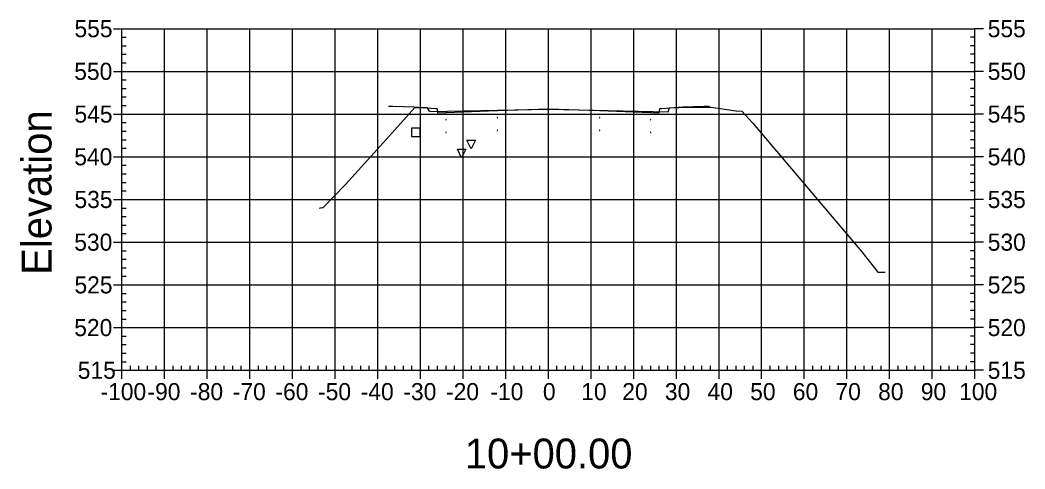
# Model space of a CAD drawing. Extents: x 708103 to 717568, y 374476 to 378707.
# Drawn here: x 708103.1 to 708338.7, y 376801.5 to 376906.6 of the extents above; entities that cross this region are included whole.
import ezdxf

# ---------------------------------------------------------------- set-up
doc = ezdxf.new("R2010")
doc.units = 0
for name, color, linetype in [('1', 7, 'Continuous'), ('10', 7, 'Continuous'), ('14', 7, 'Continuous'), ('22', 7, 'Continuous'), ('57', 7, 'Continuous'), ('60', 7, 'Continuous'), ('Existing', 7, 'Continuous')]:
    doc.layers.add(name, color=color, linetype=linetype)

msp = doc.modelspace()

# ---------------------------------------------------------------- linework, layer by layer
for points in [[(708226.93, 376885.12), (708227.03, 376885.12), (708227.03, 376885.22), (708226.93, 376885.22)], [(708202.93, 376883.28), (708203.03, 376883.28), (708203.03, 376883.38), (708202.93, 376883.38)], [(708214.93, 376883.76), (708215.03, 376883.76), (708215.03, 376883.86), (708214.93, 376883.86)], [(708226.93, 376884.12), (708227.03, 376884.12), (708227.03, 376884.22), (708226.93, 376884.22)], [(708238.93, 376883.76), (708239.03, 376883.76), (708239.03, 376883.86), (708238.93, 376883.86)], [(708250.93, 376883.28), (708251.03, 376883.28), (708251.03, 376883.38), (708250.93, 376883.38)], [(708202.93, 376880.28), (708203.03, 376880.28), (708203.03, 376880.38), (708202.93, 376880.38)], [(708214.93, 376880.76), (708215.03, 376880.76), (708215.03, 376880.86), (708214.93, 376880.86)], [(708226.93, 376881.12), (708227.03, 376881.12), (708227.03, 376881.22), (708226.93, 376881.22)], [(708238.93, 376880.76), (708239.03, 376880.76), (708239.03, 376880.86), (708238.93, 376880.86)], [(708250.93, 376880.28), (708251.03, 376880.28), (708251.03, 376880.38), (708250.93, 376880.38)]]:
    msp.add_lwpolyline(points, close=True)
at = {"layer": '1'}
for points in [[(708208.89, 376876.52), (708207.89, 376878.52), (708209.89, 376878.52)], [(708206.64, 376874.41), (708205.64, 376876.41), (708207.64, 376876.41)]]:
    msp.add_lwpolyline(points, close=True, dxfattribs=at)
at = {"layer": '10'}
msp.add_lwpolyline([(708194.88, 376879.34), (708196.88, 376879.34), (708196.88, 376881.34), (708194.88, 376881.34)], close=True, dxfattribs=at)
at = {"layer": '14'}
for points in [[(708202.98, 376884.99), (708202.98, 376885.04), (708202.98, 376884.99), (708202.93, 376884.99), (708202.98, 376884.99), (708202.98, 376884.94), (708202.98, 376884.99), (708203.03, 376884.99)], [(708214.98, 376885.47), (708214.98, 376885.52), (708214.98, 376885.47), (708214.93, 376885.47), (708214.98, 376885.47), (708214.98, 376885.42), (708214.98, 376885.47), (708215.03, 376885.47)], [(708226.98, 376885.83), (708226.98, 376885.88), (708226.98, 376885.83), (708226.93, 376885.83), (708226.98, 376885.83), (708226.98, 376885.78), (708226.98, 376885.83), (708227.03, 376885.83)], [(708238.98, 376885.47), (708238.98, 376885.52), (708238.98, 376885.47), (708238.93, 376885.47), (708238.98, 376885.47), (708238.98, 376885.42), (708238.98, 376885.47), (708239.03, 376885.47)], [(708250.98, 376884.99), (708250.98, 376885.04), (708250.98, 376884.99), (708250.93, 376884.99), (708250.98, 376884.99), (708250.98, 376884.94), (708250.98, 376884.99), (708251.03, 376884.99)], [(708264.7, 376886.26), (708264.7, 376886.31), (708264.7, 376886.26), (708264.65, 376886.26), (708264.7, 376886.26), (708264.7, 376886.21), (708264.7, 376886.26), (708264.75, 376886.26)]]:
    msp.add_lwpolyline(points, dxfattribs=at)
at = {"layer": '22'}
msp.add_lwpolyline([(708189.48, 376886.47), (708190.48, 376886.51), (708195.48, 376886.31), (708200.48, 376885.91), (708200.9, 376885.91), (708200.98, 376884.91), (708202.98, 376884.99), (708214.98, 376885.47), (708226.98, 376885.83), (708238.98, 376885.47), (708250.98, 376884.99), (708252.98, 376884.91), (708253.07, 376885.91), (708253.48, 376885.91), (708258.48, 376886.31), (708263.48, 376886.51), (708264.48, 376886.47), (708264.7, 376886.26)], dxfattribs=at)
at = {"layer": '57'}
for p, q in [((708124.98, 376904.63), (708126.98, 376904.63)), ((708126.98, 376904.63), (708326.98, 376904.63)), ((708126.98, 376824.63), (708126.98, 376904.63)), ((708126.98, 376824.63), (708126.98, 376904.63)), ((708136.98, 376824.63), (708136.98, 376904.63)), ((708146.98, 376824.63), (708146.98, 376904.63)), ((708156.98, 376824.63), (708156.98, 376904.63)), ((708166.98, 376824.63), (708166.98, 376904.63)), ((708176.98, 376824.63), (708176.98, 376904.63)), ((708186.98, 376824.63), (708186.98, 376904.63)), ((708196.98, 376824.63), (708196.98, 376904.63)), ((708206.98, 376824.63), (708206.98, 376904.63)), ((708216.98, 376824.63), (708216.98, 376904.63)), ((708226.98, 376824.63), (708226.98, 376904.63)), ((708236.98, 376824.63), (708236.98, 376904.63)), ((708246.98, 376824.63), (708246.98, 376904.63)), ((708256.98, 376824.63), (708256.98, 376904.63)), ((708266.98, 376824.63), (708266.98, 376904.63)), ((708276.98, 376824.63), (708276.98, 376904.63)), ((708286.98, 376824.63), (708286.98, 376904.63)), ((708296.98, 376824.63), (708296.98, 376904.63)), ((708306.98, 376824.63), (708306.98, 376904.63)), ((708316.98, 376824.63), (708316.98, 376904.63)), ((708326.98, 376824.63), (708326.98, 376904.63)), ((708326.98, 376824.63), (708326.98, 376904.63)), ((708328.98, 376904.63), (708326.98, 376904.63)), ((708126.98, 376902.63), (708127.98, 376902.63)), ((708326.98, 376902.63), (708325.98, 376902.63)), ((708126.98, 376900.63), (708127.98, 376900.63)), ((708126.98, 376898.63), (708127.98, 376898.63)), ((708326.98, 376900.63), (708325.98, 376900.63)), ((708326.98, 376898.63), (708325.98, 376898.63)), ((708126.98, 376896.63), (708127.98, 376896.63)), ((708326.98, 376896.63), (708325.98, 376896.63)), ((708124.98, 376894.63), (708126.98, 376894.63)), ((708126.98, 376894.63), (708326.98, 376894.63)), ((708328.98, 376894.63), (708326.98, 376894.63)), ((708126.98, 376892.63), (708127.98, 376892.63)), ((708326.98, 376892.63), (708325.98, 376892.63)), ((708126.98, 376890.63), (708127.98, 376890.63)), ((708326.98, 376890.63), (708325.98, 376890.63)), ((708126.98, 376888.63), (708127.98, 376888.63)), ((708326.98, 376888.63), (708325.98, 376888.63)), ((708124.98, 376884.63), (708126.98, 376884.63)), ((708126.98, 376886.63), (708127.98, 376886.63)), ((708126.98, 376884.63), (708326.98, 376884.63)), ((708326.98, 376886.63), (708325.98, 376886.63)), ((708328.98, 376884.63), (708326.98, 376884.63)), ((708126.98, 376882.63), (708127.98, 376882.63)), ((708326.98, 376882.63), (708325.98, 376882.63)), ((708126.98, 376880.63), (708127.98, 376880.63)), ((708326.98, 376880.63), (708325.98, 376880.63)), ((708126.98, 376878.63), (708127.98, 376878.63)), ((708326.98, 376878.63), (708325.98, 376878.63)), ((708126.98, 376876.63), (708127.98, 376876.63)), ((708326.98, 376876.63), (708325.98, 376876.63)), ((708124.98, 376874.63), (708126.98, 376874.63)), ((708126.98, 376874.63), (708326.98, 376874.63)), ((708328.98, 376874.63), (708326.98, 376874.63)), ((708126.98, 376872.63), (708127.98, 376872.63)), ((708126.98, 376870.63), (708127.98, 376870.63)), ((708326.98, 376872.63), (708325.98, 376872.63)), ((708326.98, 376870.63), (708325.98, 376870.63)), ((708126.98, 376868.63), (708127.98, 376868.63)), ((708326.98, 376868.63), (708325.98, 376868.63)), ((708126.98, 376866.63), (708127.98, 376866.63)), ((708326.98, 376866.63), (708325.98, 376866.63)), ((708124.98, 376864.63), (708126.98, 376864.63)), ((708126.98, 376864.63), (708326.98, 376864.63)), ((708328.98, 376864.63), (708326.98, 376864.63)), ((708126.98, 376862.63), (708127.98, 376862.63)), ((708326.98, 376862.63), (708325.98, 376862.63)), ((708126.98, 376860.63), (708127.98, 376860.63)), ((708126.98, 376858.63), (708127.98, 376858.63)), ((708326.98, 376860.63), (708325.98, 376860.63)), ((708326.98, 376858.63), (708325.98, 376858.63)), ((708126.98, 376856.63), (708127.98, 376856.63)), ((708326.98, 376856.63), (708325.98, 376856.63)), ((708124.98, 376854.63), (708126.98, 376854.63)), ((708126.98, 376854.63), (708326.98, 376854.63)), ((708328.98, 376854.63), (708326.98, 376854.63)), ((708126.98, 376852.63), (708127.98, 376852.63)), ((708326.98, 376852.63), (708325.98, 376852.63)), ((708126.98, 376850.63), (708127.98, 376850.63)), ((708326.98, 376850.63), (708325.98, 376850.63)), ((708126.98, 376848.63), (708127.98, 376848.63)), ((708326.98, 376848.63), (708325.98, 376848.63)), ((708124.98, 376844.63), (708126.98, 376844.63)), ((708126.98, 376846.63), (708127.98, 376846.63)), ((708126.98, 376844.63), (708326.98, 376844.63)), ((708326.98, 376846.63), (708325.98, 376846.63)), ((708328.98, 376844.63), (708326.98, 376844.63)), ((708126.98, 376842.63), (708127.98, 376842.63)), ((708326.98, 376842.63), (708325.98, 376842.63)), ((708126.98, 376840.63), (708127.98, 376840.63)), ((708326.98, 376840.63), (708325.98, 376840.63)), ((708126.98, 376838.63), (708127.98, 376838.63)), ((708326.98, 376838.63), (708325.98, 376838.63)), ((708126.98, 376836.63), (708127.98, 376836.63)), ((708326.98, 376836.63), (708325.98, 376836.63)), ((708124.98, 376834.63), (708126.98, 376834.63)), ((708126.98, 376834.63), (708326.98, 376834.63)), ((708126.98, 376832.63), (708127.98, 376832.63)), ((708326.98, 376832.63), (708325.98, 376832.63)), ((708328.98, 376834.63), (708326.98, 376834.63)), ((708126.98, 376830.63), (708127.98, 376830.63)), ((708326.98, 376830.63), (708325.98, 376830.63)), ((708126.98, 376828.63), (708127.98, 376828.63)), ((708326.98, 376828.63), (708325.98, 376828.63)), ((708126.98, 376826.63), (708127.98, 376826.63)), ((708128.98, 376824.63), (708128.98, 376825.63)), ((708130.98, 376824.63), (708130.98, 376825.63)), ((708132.98, 376824.63), (708132.98, 376825.63)), ((708134.98, 376824.63), (708134.98, 376825.63)), ((708138.98, 376824.63), (708138.98, 376825.63)), ((708140.98, 376824.63), (708140.98, 376825.63)), ((708142.98, 376824.63), (708142.98, 376825.63)), ((708144.98, 376824.63), (708144.98, 376825.63)), ((708148.98, 376824.63), (708148.98, 376825.63)), ((708150.98, 376824.63), (708150.98, 376825.63)), ((708152.98, 376824.63), (708152.98, 376825.63)), ((708154.98, 376824.63), (708154.98, 376825.63)), ((708158.98, 376824.63), (708158.98, 376825.63)), ((708160.98, 376824.63), (708160.98, 376825.63)), ((708162.98, 376824.63), (708162.98, 376825.63)), ((708164.98, 376824.63), (708164.98, 376825.63)), ((708168.98, 376824.63), (708168.98, 376825.63)), ((708170.98, 376824.63), (708170.98, 376825.63)), ((708172.98, 376824.63), (708172.98, 376825.63)), ((708174.98, 376824.63), (708174.98, 376825.63)), ((708178.98, 376824.63), (708178.98, 376825.63)), ((708180.98, 376824.63), (708180.98, 376825.63)), ((708182.98, 376824.63), (708182.98, 376825.63)), ((708184.98, 376824.63), (708184.98, 376825.63)), ((708188.98, 376824.63), (708188.98, 376825.63)), ((708190.98, 376824.63), (708190.98, 376825.63)), ((708192.98, 376824.63), (708192.98, 376825.63)), ((708194.98, 376824.63), (708194.98, 376825.63)), ((708198.98, 376824.63), (708198.98, 376825.63)), ((708200.98, 376824.63), (708200.98, 376825.63)), ((708202.98, 376824.63), (708202.98, 376825.63)), ((708204.98, 376824.63), (708204.98, 376825.63)), ((708208.98, 376824.63), (708208.98, 376825.63)), ((708210.98, 376824.63), (708210.98, 376825.63)), ((708212.98, 376824.63), (708212.98, 376825.63)), ((708214.98, 376824.63), (708214.98, 376825.63)), ((708218.98, 376824.63), (708218.98, 376825.63)), ((708220.98, 376824.63), (708220.98, 376825.63)), ((708222.98, 376824.63), (708222.98, 376825.63)), ((708224.98, 376824.63), (708224.98, 376825.63)), ((708228.98, 376824.63), (708228.98, 376825.63)), ((708230.98, 376824.63), (708230.98, 376825.63)), ((708232.98, 376824.63), (708232.98, 376825.63)), ((708234.98, 376824.63), (708234.98, 376825.63)), ((708238.98, 376824.63), (708238.98, 376825.63)), ((708240.98, 376824.63), (708240.98, 376825.63)), ((708242.98, 376824.63), (708242.98, 376825.63)), ((708244.98, 376824.63), (708244.98, 376825.63)), ((708248.98, 376824.63), (708248.98, 376825.63)), ((708250.98, 376824.63), (708250.98, 376825.63)), ((708252.98, 376824.63), (708252.98, 376825.63)), ((708254.98, 376824.63), (708254.98, 376825.63)), ((708258.98, 376824.63), (708258.98, 376825.63)), ((708260.98, 376824.63), (708260.98, 376825.63)), ((708262.98, 376824.63), (708262.98, 376825.63)), ((708264.98, 376824.63), (708264.98, 376825.63)), ((708268.98, 376824.63), (708268.98, 376825.63)), ((708270.98, 376824.63), (708270.98, 376825.63)), ((708272.98, 376824.63), (708272.98, 376825.63)), ((708274.98, 376824.63), (708274.98, 376825.63)), ((708278.98, 376824.63), (708278.98, 376825.63)), ((708280.98, 376824.63), (708280.98, 376825.63)), ((708282.98, 376824.63), (708282.98, 376825.63)), ((708284.98, 376824.63), (708284.98, 376825.63)), ((708288.98, 376824.63), (708288.98, 376825.63)), ((708290.98, 376824.63), (708290.98, 376825.63)), ((708292.98, 376824.63), (708292.98, 376825.63)), ((708294.98, 376824.63), (708294.98, 376825.63)), ((708298.98, 376824.63), (708298.98, 376825.63)), ((708300.98, 376824.63), (708300.98, 376825.63)), ((708302.98, 376824.63), (708302.98, 376825.63)), ((708304.98, 376824.63), (708304.98, 376825.63)), ((708308.98, 376824.63), (708308.98, 376825.63)), ((708310.98, 376824.63), (708310.98, 376825.63)), ((708312.98, 376824.63), (708312.98, 376825.63)), ((708314.98, 376824.63), (708314.98, 376825.63)), ((708318.98, 376824.63), (708318.98, 376825.63)), ((708320.98, 376824.63), (708320.98, 376825.63)), ((708322.98, 376824.63), (708322.98, 376825.63)), ((708324.98, 376824.63), (708324.98, 376825.63)), ((708326.98, 376826.63), (708325.98, 376826.63)), ((708124.98, 376824.63), (708126.98, 376824.63)), ((708126.98, 376824.63), (708326.98, 376824.63)), ((708126.98, 376824.63), (708326.98, 376824.63)), ((708126.98, 376822.63), (708126.98, 376824.63)), ((708136.98, 376822.63), (708136.98, 376824.63)), ((708146.98, 376822.63), (708146.98, 376824.63)), ((708156.98, 376822.63), (708156.98, 376824.63)), ((708166.98, 376822.63), (708166.98, 376824.63)), ((708176.98, 376822.63), (708176.98, 376824.63)), ((708186.98, 376822.63), (708186.98, 376824.63)), ((708196.98, 376822.63), (708196.98, 376824.63)), ((708206.98, 376822.63), (708206.98, 376824.63)), ((708216.98, 376822.63), (708216.98, 376824.63)), ((708226.98, 376822.63), (708226.98, 376824.63)), ((708236.98, 376822.63), (708236.98, 376824.63)), ((708246.98, 376822.63), (708246.98, 376824.63)), ((708256.98, 376822.63), (708256.98, 376824.63)), ((708266.98, 376822.63), (708266.98, 376824.63)), ((708276.98, 376822.63), (708276.98, 376824.63)), ((708286.98, 376822.63), (708286.98, 376824.63)), ((708296.98, 376822.63), (708296.98, 376824.63)), ((708306.98, 376822.63), (708306.98, 376824.63)), ((708316.98, 376822.63), (708316.98, 376824.63)), ((708326.98, 376822.63), (708326.98, 376824.63)), ((708328.98, 376824.63), (708326.98, 376824.63))]:
    msp.add_line(p, q, dxfattribs=at)
at = {"layer": 'Existing'}
msp.add_lwpolyline([(708173.33, 376862.61), (708173.52, 376862.64), (708174.16, 376862.72), (708179.4, 376868.17), (708188.32, 376877.95), (708195.64, 376886.15), (708198.51, 376886.19), (708198.97, 376885.35), (708199.2, 376885.35), (708199.23, 376885.27), (708226.98, 376885.8), (708255.03, 376885.13), (708255.41, 376886.1), (708255.42, 376886.12), (708255.49, 376886.12), (708259.61, 376886.22), (708259.72, 376886.22), (708259.85, 376886.23), (708265.11, 376886.26), (708265.18, 376886.25), (708270.89, 376885.4), (708270.97, 376885.39), (708272.37, 376885.31), (708274.85, 376882.58), (708300.48, 376852.35), (708304.2, 376847.64), (708305.91, 376847.59)], dxfattribs=at)

# ---------------------------------------------------------------- texts
at = {"layer": '1'}
msp.add_text('10+00.00', height=7, dxfattribs=at).set_placement((708207.39, 376801.63))
at = {"layer": '14'}
for p in [(708190.45, 376886.46), (708190.45, 376885.8), (708195.45, 376885.6), (708258.45, 376885.6), (708263.45, 376886.46), (708263.45, 376885.8)]:
    msp.add_text('+', height=0.1, dxfattribs=at).set_placement(p)
at = {"layer": '57'}
for s, p in [('555', (708115.86, 376902.63)), ('555', (708329.98, 376902.63)), ('550', (708115.81, 376892.63)), ('550', (708329.98, 376892.63)), ('545', (708115.86, 376882.63)), ('545', (708329.98, 376882.63)), ('540', (708115.81, 376872.63)), ('540', (708329.98, 376872.63)), ('535', (708115.86, 376862.63)), ('535', (708329.98, 376862.63)), ('530', (708115.81, 376852.63)), ('530', (708329.98, 376852.63)), ('525', (708115.86, 376842.63)), ('525', (708329.98, 376842.63)), ('520', (708115.81, 376832.63)), ('520', (708329.98, 376832.63)), ('515', (708116.63, 376822.63)), ('515', (708329.98, 376822.63)), ('-100', (708121.97, 376817.63)), ('-90', (708132.98, 376817.63)), ('-80', (708142.98, 376817.63)), ('-70', (708152.98, 376817.63)), ('-60', (708162.98, 376817.63)), ('-50', (708172.98, 376817.63)), ('-40', (708182.98, 376817.63)), ('-30', (708192.98, 376817.63)), ('-20', (708202.98, 376817.63)), ('-10', (708213.37, 376817.63)), ('0', (708225.69, 376817.63)), ('10', (708234.68, 376817.63)), ('20', (708244.29, 376817.63)), ('30', (708254.29, 376817.63)), ('40', (708264.29, 376817.63)), ('50', (708274.29, 376817.63)), ('60', (708284.29, 376817.63)), ('70', (708294.29, 376817.63)), ('80', (708304.29, 376817.63)), ('90', (708314.29, 376817.63)), ('100', (708323.28, 376817.63))]:
    msp.add_text(s, height=4, dxfattribs=at).set_placement(p)
at = {"layer": '60'}
msp.add_text('Elevation', height=7, rotation=90, dxfattribs=at).set_placement((708110.48, 376846.99))

doc.saveas('drawing.dxf')
